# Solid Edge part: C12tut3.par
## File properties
Author: CADCIM
Template: ansi part.par
Last saved by: Rajat Kamboj
Revision: 12
Application: Solid Edge
Accuracy: 0.990
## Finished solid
Body 1: solid body, 13 faces, 19 edges, 8 vertices.
  Faces by surface: plane 9, cylinder 4
  Edges by curve: line 10, circle 8, ellipse 1
Bounding box of the edges (mm): 31.750 x 82.544 x 31.750, from (-15.875, -77.8163, -15.875) to (15.875, 4.7283, 15.875).
Cylindrical faces by radius (mm): R5.5944 x1, R6.35 x1, R7.9375 x1, R15.875 x1
Planar faces by outward normal: +x 1, +y 1, +z 1, -x 1, -y 4, oblique 1
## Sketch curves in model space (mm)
line (-22.2359, -0.0325, 12.7) -> (-22.2334, -4.7925, 7.935)
line (-22.2322, -77.8163, 5.5531) -> (-22.2323, -0.0289, 5.77)
line (-22.2262, -77.8103, -5.6356) -> (-22.2263, -0.0229, -5.5751)
line (-22.2326, -68.2917, 6.3138) -> (-22.2326, -77.8167, 6.3087)
line (-22.2326, -77.8167, 6.3087) -> (-22.2258, -77.8099, -6.3913)
line (-22.2258, -68.2849, -6.3862) -> (-22.2258, -77.8099, -6.3913)
line (-22.2376, -0.0342, 15.875) -> (-22.2208, -0.0174, -15.875)
line (-22.2376, 4.7283, 15.8775) -> (-22.2376, -0.0342, 15.875)
line (-22.2376, 4.7283, 15.8775) -> (-22.2208, 4.7451, -15.8725)
line (-22.2208, 4.7451, -15.8725) -> (-22.2208, -0.0174, -15.875)
line (-22.225, -0.0216, -7.9375) -> (-22.225, -68.2841, -7.9737)
line (-22.2334, -0.03, 7.9375) -> (-22.2334, -68.2925, 7.9013)
line (-22.2334, -68.2925, 7.9013) -> (-22.225, -68.2841, -7.9737)
line (0, 0, 22.225) -> (0, 0, -22.225)
line (22.225, 0, 0) -> (-22.225, 0, 0)
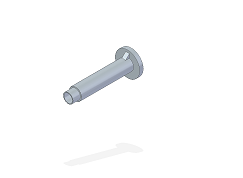
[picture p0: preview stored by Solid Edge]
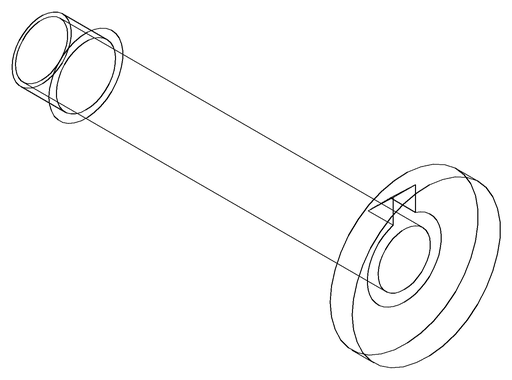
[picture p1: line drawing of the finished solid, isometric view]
